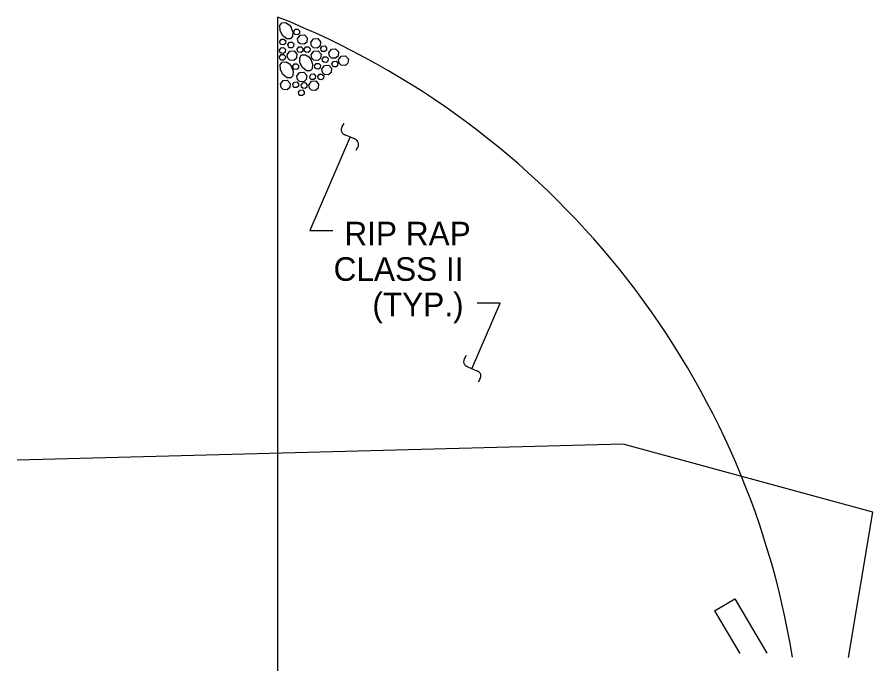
# Model space of a CAD drawing. Extents: x 471 to 2034, y -623 to 126.
# Drawn here: x 1523.86 to 1560.1, y -9.99 to 17.38 of the extents above; entities that cross this region are included whole.
import ezdxf

# ---------------------------------------------------------------- set-up
doc = ezdxf.new("R2010")
doc.units = 0
for name, color, linetype in [('Arrowhead Terminators CELL', 7, 'Continuous'), ('Dimension Lines', 7, 'Continuous'), ('Exist Hydro Stream or Body of Water', 7, 'Continuous'), ('Exist Structure Major Bridge Seam', 7, 'Continuous'), ('Miscellaneous Lines CELL', 7, 'Continuous'), ('Sup Concrete Girder Lines', 7, 'Continuous'), ('Text', 7, 'Continuous')]:
    doc.layers.add(name, color=color, linetype=linetype)

msp = doc.modelspace()

# ---------------------------------------------------------------- linework, layer by layer
at = {"layer": 'Arrowhead Terminators CELL'}
for p, q in [((1537.629, 12.751), (1537.704, 12.878)), ((1538.141, 12.233), (1537.735, 12.408)), ((1538.21, 11.754), (1538.271, 11.846)), ((1542.875, 3.06), (1542.814, 2.968)), ((1542.944, 2.58), (1543.35, 2.405)), ((1543.456, 2.062), (1543.381, 1.936))]:
    msp.add_line(p, q, dxfattribs=at)
for centre, radius, start, end in [((1537.806, 12.616), 0.221, 142.4705, 250.7561), ((1538.069, 11.995), 0.249, 323.4021, 73.201), ((1543.016, 2.818), 0.249, 143.4021, 253.201), ((1543.279, 2.197), 0.221, 322.4705, 70.7561)]:
    msp.add_arc(centre, radius, start, end, dxfattribs=at)
at = {"layer": 'Dimension Lines'}
for p, q in [((1537.968, 12.313), (1536.255, 8.348)), ((1536.255, 8.348), (1537.227, 8.348)), ((1543.117, 2.5), (1544.315, 5.274)), ((1544.315, 5.274), (1543.344, 5.274))]:
    msp.add_line(p, q, dxfattribs=at)
at = {"layer": 'Exist Hydro Stream or Body of Water'}
msp.add_lwpolyline([(1559.07, -9.715), (1560.097, -3.568), (1549.524, -0.687), (1523.86, -1.364)], dxfattribs=at)
at = {"layer": 'Exist Structure Major Bridge Seam'}
for p, q in [((1553.394, -7.738), (1554.256, -7.232)), ((1554.256, -7.232), (1555.61, -9.535)), ((1553.394, -7.738), (1554.461, -9.553))]:
    msp.add_line(p, q, dxfattribs=at)
at = {"layer": 'Miscellaneous Lines CELL'}
for points in [[(1535.454, 16.961), (1535.537, 16.752), (1535.52, 16.559), (1535.433, 16.467), (1535.277, 16.47), (1535.1, 16.609), (1534.992, 16.824), (1534.989, 17.026), (1535.07, 17.14), (1535.231, 17.151), (1535.375, 17.058), (1535.459, 16.953)], [(1535.572, 16.779), (1535.639, 16.875), (1535.747, 16.881), (1535.821, 16.804), (1535.811, 16.695), (1535.744, 16.64), (1535.638, 16.648), (1535.588, 16.696), (1535.572, 16.779)], [(1534.982, 16.351), (1535.05, 16.446), (1535.157, 16.452), (1535.232, 16.375), (1535.221, 16.267), (1535.154, 16.211), (1535.048, 16.219), (1534.999, 16.267), (1534.982, 16.351)], [(1535.33, 16.223), (1535.397, 16.318), (1535.504, 16.324), (1535.579, 16.247), (1535.568, 16.139), (1535.502, 16.084), (1535.396, 16.091), (1535.346, 16.14), (1535.33, 16.223)], [(1535.734, 16.467), (1535.846, 16.626), (1536.025, 16.636), (1536.149, 16.507), (1536.131, 16.327), (1536.021, 16.235), (1535.844, 16.247), (1535.761, 16.328), (1535.734, 16.467)], [(1536.297, 16.304), (1536.409, 16.463), (1536.588, 16.473), (1536.713, 16.344), (1536.695, 16.164), (1536.584, 16.072), (1536.407, 16.085), (1536.324, 16.165), (1536.297, 16.304)], [(1534.972, 15.99), (1535.039, 16.086), (1535.147, 16.092), (1535.221, 16.014), (1535.21, 15.906), (1535.144, 15.851), (1535.038, 15.859), (1534.988, 15.907), (1534.972, 15.99)], [(1535.295, 15.782), (1535.407, 15.942), (1535.586, 15.952), (1535.71, 15.823), (1535.692, 15.642), (1535.582, 15.551), (1535.405, 15.563), (1535.322, 15.644), (1535.295, 15.782)], [(1535.715, 16.028), (1535.783, 16.124), (1535.89, 16.13), (1535.965, 16.052), (1535.954, 15.944), (1535.887, 15.889), (1535.781, 15.897), (1535.732, 15.945), (1535.715, 16.028)], [(1536.019, 16.028), (1536.087, 16.124), (1536.194, 16.13), (1536.269, 16.052), (1536.258, 15.944), (1536.191, 15.889), (1536.085, 15.897), (1536.036, 15.945), (1536.019, 16.028)], [(1536.314, 15.782), (1536.426, 15.942), (1536.605, 15.952), (1536.73, 15.823), (1536.712, 15.642), (1536.601, 15.551), (1536.424, 15.563), (1536.341, 15.644), (1536.314, 15.782)], [(1536.717, 16.064), (1536.784, 16.159), (1536.891, 16.166), (1536.966, 16.088), (1536.955, 15.98), (1536.889, 15.925), (1536.783, 15.932), (1536.733, 15.981), (1536.717, 16.064)], [(1537.057, 15.872), (1537.169, 16.031), (1537.348, 16.041), (1537.472, 15.912), (1537.454, 15.732), (1537.343, 15.64), (1537.167, 15.653), (1537.084, 15.733), (1537.057, 15.872)], [(1534.972, 15.7), (1535.039, 15.796), (1535.147, 15.802), (1535.221, 15.724), (1535.21, 15.616), (1535.144, 15.561), (1535.038, 15.568), (1534.988, 15.617), (1534.972, 15.7)], [(1536.292, 15.602), (1536.375, 15.392), (1536.359, 15.2), (1536.272, 15.108), (1536.116, 15.111), (1535.938, 15.25), (1535.831, 15.465), (1535.827, 15.667), (1535.908, 15.781), (1536.069, 15.792), (1536.213, 15.699), (1536.298, 15.593)], [(1536.781, 15.608), (1536.849, 15.704), (1536.956, 15.71), (1537.031, 15.633), (1537.02, 15.524), (1536.954, 15.469), (1536.847, 15.477), (1536.798, 15.525), (1536.781, 15.608)], [(1537.472, 15.57), (1537.584, 15.73), (1537.763, 15.74), (1537.888, 15.611), (1537.87, 15.43), (1537.759, 15.338), (1537.583, 15.351), (1537.499, 15.432), (1537.473, 15.57)], [(1535.469, 15.306), (1535.552, 15.096), (1535.535, 14.903), (1535.448, 14.812), (1535.292, 14.815), (1535.115, 14.954), (1535.007, 15.168), (1535.004, 15.371), (1535.085, 15.484), (1535.246, 15.495), (1535.39, 15.403), (1535.474, 15.297)], [(1535.532, 15.306), (1535.599, 15.402), (1535.707, 15.408), (1535.781, 15.331), (1535.77, 15.222), (1535.704, 15.167), (1535.598, 15.175), (1535.548, 15.223), (1535.532, 15.306)], [(1536.456, 15.324), (1536.524, 15.42), (1536.631, 15.426), (1536.706, 15.349), (1536.695, 15.24), (1536.628, 15.185), (1536.522, 15.193), (1536.473, 15.241), (1536.456, 15.324)], [(1536.763, 15.178), (1536.875, 15.337), (1537.054, 15.347), (1537.178, 15.218), (1537.16, 15.038), (1537.05, 14.946), (1536.873, 14.959), (1536.79, 15.039), (1536.763, 15.178)], [(1537.192, 15.413), (1537.259, 15.509), (1537.367, 15.515), (1537.441, 15.437), (1537.431, 15.329), (1537.364, 15.274), (1537.258, 15.281), (1537.208, 15.33), (1537.192, 15.413)], [(1535.708, 14.879), (1535.82, 15.038), (1535.999, 15.048), (1536.123, 14.919), (1536.105, 14.739), (1535.995, 14.647), (1535.818, 14.66), (1535.735, 14.74), (1535.708, 14.879)], [(1536.248, 14.877), (1536.315, 14.972), (1536.422, 14.978), (1536.497, 14.901), (1536.486, 14.793), (1536.42, 14.737), (1536.314, 14.745), (1536.264, 14.793), (1536.248, 14.876)], [(1536.592, 14.872), (1536.66, 14.967), (1536.767, 14.974), (1536.841, 14.896), (1536.831, 14.788), (1536.764, 14.733), (1536.658, 14.74), (1536.609, 14.789), (1536.592, 14.872)], [(1535.01, 14.541), (1535.122, 14.7), (1535.301, 14.71), (1535.426, 14.581), (1535.408, 14.401), (1535.297, 14.309), (1535.121, 14.322), (1535.037, 14.402), (1535.01, 14.541)], [(1535.532, 14.541), (1535.599, 14.637), (1535.707, 14.643), (1535.781, 14.566), (1535.77, 14.457), (1535.704, 14.402), (1535.598, 14.41), (1535.548, 14.458), (1535.532, 14.541)], [(1535.886, 14.508), (1535.953, 14.604), (1536.061, 14.61), (1536.135, 14.533), (1536.124, 14.424), (1536.058, 14.369), (1535.952, 14.377), (1535.902, 14.425), (1535.886, 14.508)], [(1536.212, 14.511), (1536.324, 14.67), (1536.503, 14.681), (1536.627, 14.552), (1536.609, 14.371), (1536.499, 14.279), (1536.322, 14.292), (1536.239, 14.372), (1536.212, 14.511)], [(1535.771, 14.204), (1535.839, 14.299), (1535.946, 14.306), (1536.021, 14.228), (1536.01, 14.12), (1535.944, 14.065), (1535.838, 14.072), (1535.788, 14.121), (1535.771, 14.204)]]:
    msp.add_lwpolyline(points, dxfattribs=at)
at = {"layer": 'Sup Concrete Girder Lines'}
msp.add_line((1534.907, -14.824), (1534.907, 17.384), dxfattribs=at)
msp.add_arc((1521.869, -15.409), 35.289, 9.311, 68.3178, dxfattribs=at)

# ---------------------------------------------------------------- texts
at = {"layer": 'Text'}
for s, p in [('RIP RAP', (1537.718, 7.722)), ('CLASS II', (1537.262, 6.222)), ('(TYP.)', (1538.903, 4.722))]:
    msp.add_text(s, height=1, dxfattribs=at).set_placement(p)

doc.saveas('drawing.dxf')
